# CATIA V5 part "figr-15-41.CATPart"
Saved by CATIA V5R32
Part number: Part1
Bounding box of the stored display mesh (mm): x -55.204 to 69.266, y -33.79 to 44.107, z 0 to 118.408
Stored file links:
  D:\PROJECTS\Project 2022\CATIA V5 6R 2022\Resources\Part Files\c15_catia_v5_6r2022_prt\figr-15-41.CATPart
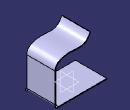
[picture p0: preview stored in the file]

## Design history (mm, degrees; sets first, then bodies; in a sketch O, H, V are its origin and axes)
SheetMetalParameters1: Thickness 2, BendRadius 4, KFactor 0.400515 {= log(min(100,max(20*SheetMetalParameters1.BendRadius,SheetMetalParameters1.Thickness)/SheetMetalParameters1.Thickness))/log(100)/2}, ReliefRadialLength 1, ReliefAxialLength 2, MinimumBendRadius 0
Body1 (main body)
  Sketch1 on xy-plane, origin (0, 0, 0), H (1, 0, 0), V (0, 1, 0)
    line L1 (-55.2037, 44.1067) -> (69.266, 44.1067)
    line L2 (69.266, 44.1067) -> (69.266, -33.7896)
    line L3 (69.266, -33.7896) -> (-55.2037, -33.7896)
    line L4 (-55.2037, -33.7896) -> (-55.2037, 44.1067)
    horizontal: L1 H, L3 H
    vertical: L2 V, L4 V
  Wall1: Thickness 2, Profile Sketch1, OffsetValue 0
  d_NewWallOnEdge1: NewWallOnEdge_Length 77.8964, NewWallOnEdge_HeightLimitOffset 0, NewWallOnEdge_WidthOffset1 -4, NewWallOnEdge_WidthOffset2 -4, NewWallOnEdge_Angle 90, NewWallOnEdge_BendRadiusValue 4 {= SheetMetalParameters1.BendRadius}, NewWallOnEdge_BendTable SheetMetalParameters1, NewWallOnEdge_Edge edge [face of Wall1 | face of Wall1], NewWallOnEdge_GapValue 0, KFacteur 0.400515 {= log(min(100,max(20*d_NewWallOnEdge1.Radius,SheetMetalParameters1.Thickness)/SheetMetalParameters1.Thickness))/log(100)/2}
  Sketch2 on face of d_NewWallOnEdge1, origin (0, 40.1067, 0), H (-1, 0, 0), V (0, 0, 1)
    spline S1 through (-69.266, 77.8964) (-67.9767, 84.9607) (-48.7678, 98.5965) (6.1586, 103.3856) (17.3621, 118.4076)
    reference projected line E1 (-69.266, 6) -> (-69.266, 77.8964) from edge [face of d_NewWallOnEdge1 | face of d_NewWallOnEdge1]
    reference projected line E2 (-69.266, 6) -> (-69.266, 77.8964) from edge [face of d_NewWallOnEdge1 | face of d_NewWallOnEdge1]
    reference projected point E3 (-69.266, 77.8964) from vertex [face of d_NewWallOnEdge1 | face of d_NewWallOnEdge1 | face of d_NewWallOnEdge1]
    point P1 (-69.266, 77.8964)
    coincidence: P1 E1, P1 E3
    tangency: S1 E2
  Flange1: Guide edge [face of d_NewWallOnEdge1 | face of d_NewWallOnEdge1], KFacteur 0.400515 {= SheetMetalParameters1.KFactor}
